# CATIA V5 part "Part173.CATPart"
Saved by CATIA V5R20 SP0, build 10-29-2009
Part number: FA 126700-1
Revision: ANY
Definition: UNKNOWN
Nomenclature: FA 126700-1
Source: Unknown
Bounding box of the stored display mesh (mm): x -3.804 to 3.804, y 0.2 to 2.5, z -4 to 4
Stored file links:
  C:\Users\Utente\Desktop\IO LAVORO\3D X SITO CF\CUMSA\3D files FA\FA 126708-20\Part173.CATPart
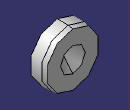
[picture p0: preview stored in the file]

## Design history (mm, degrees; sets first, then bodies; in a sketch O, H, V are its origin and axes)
Body1 "Cortar-Extruir1" (main body)
  Solid1: solid without history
